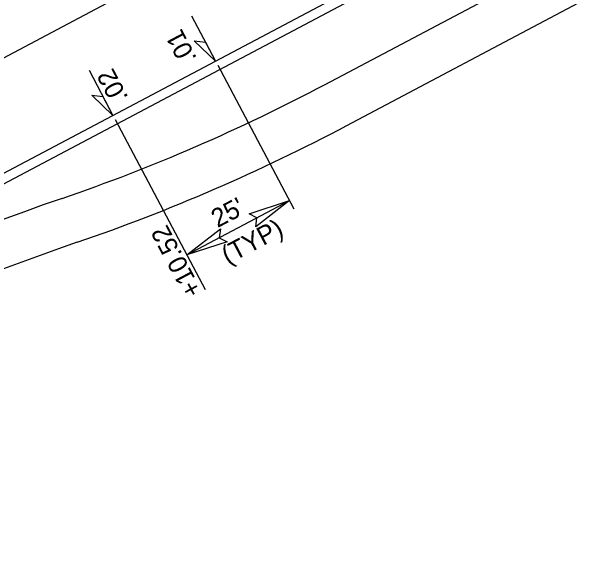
# Model space of a CAD drawing. Extents: x 1486489 to 1490134, y 497089 to 500876.
# Drawn here: x 1488009.9 to 1488132.1, y 498381.4 to 498502.1 of the extents above; entities that cross this region are included whole.
import ezdxf

# ---------------------------------------------------------------- set-up
doc = ezdxf.new("R2010")
doc.units = 0
for name, color, linetype in [('Prop Horizontal Alignment Station Label', 7, 'Continuous'), ('Scratch_Level_3', 7, 'Continuous'), ('Scratch_Level_5', 7, 'Continuous'), ('Sheet Block Title CELL', 7, 'Continuous'), ('Sheet Sticker Exception Certification CELL', 7, 'Continuous')]:
    doc.layers.add(name, color=color, linetype=linetype)

msp = doc.modelspace()

# ---------------------------------------------------------------- linework, layer by layer
at = {"layer": 'Prop Horizontal Alignment Station Label'}
for p, q in [((1488077.52, 498486.32), (1488127.44, 498512.75)), ((1488082.2, 498477.48), (1488132.12, 498503.91))]:
    msp.add_line(p, q, dxfattribs=at)
for centre, radius, start, end in [((1487892.72, 498835.43), 395, 288.9278, 297.895), ((1487892.72, 498835.43), 405, 288.9278, 297.895), ((1488184.66, 497984.09), 505, 108.9278, 124.5146), ((1488184.66, 497984.09), 495, 108.9278, 124.5146)]:
    msp.add_arc(centre, radius, start, end, dxfattribs=at)
at = {"layer": 'Scratch_Level_3'}
for p, q in [((1488048.76, 498501.08), (1488053.91, 498491.36)), ((1488054.37, 498490.48), (1488070.75, 498459.54)), ((1488026.67, 498489.39), (1488031.81, 498479.66)), ((1488032.28, 498478.79), (1488051.68, 498442.14)), ((1488047.72, 498449.62), (1488069.82, 498461.31))]:
    msp.add_line(p, q, dxfattribs=at)
for points in [[(1488053.91, 498491.36), (1488049.34, 498495.73), (1488051.75, 498495.45)], [(1488031.81, 498479.66), (1488027.24, 498484.03), (1488029.65, 498483.75)], [(1488061.14, 498458.47), (1488069.82, 498461.31), (1488062.57, 498455.66), (1488062.83, 498457.62)], [(1488056.4, 498452.46), (1488047.72, 498449.62), (1488054.97, 498455.26), (1488054.7, 498453.31)]]:
    msp.add_lwpolyline(points, close=True, dxfattribs=at)
at = {"layer": 'Scratch_Level_5'}
msp.add_line((1487850.46, 498381.4), (1488121.13, 498524.68), dxfattribs=at)
at = {"layer": 'Sheet Block Title CELL'}
msp.add_line((1487839.23, 498402.61), (1488109.9, 498545.89), dxfattribs=at)
at = {"layer": 'Sheet Sticker Exception Certification CELL'}
msp.add_line((1487849.52, 498383.17), (1488120.19, 498526.45), dxfattribs=at)

# ---------------------------------------------------------------- texts
at = {"layer": 'Scratch_Level_3'}
for s, rotation, p in [('.01', 117.895, (1488049.97, 498491.96)), ('.02', 117.895, (1488035.19, 498483.51)), ("25'", 27.895, (1488054.34, 498455.38)), ('+10.52', 117.895, (1488051.09, 498441.78)), ('(TYP)', 27.895, (1488056.54, 498447.5))]:
    msp.add_text(s, height=4, rotation=rotation, dxfattribs=at).set_placement(p)

doc.saveas('drawing.dxf')
